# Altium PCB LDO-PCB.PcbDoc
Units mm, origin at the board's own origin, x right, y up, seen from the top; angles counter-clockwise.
Board outline 26 x 11 mm, 2 copper layers (Top Layer, Bottom Layer); 5 components, 3 nets, 17 pads, 4 vias.
Unrouted connection lines stored in the file: 4.
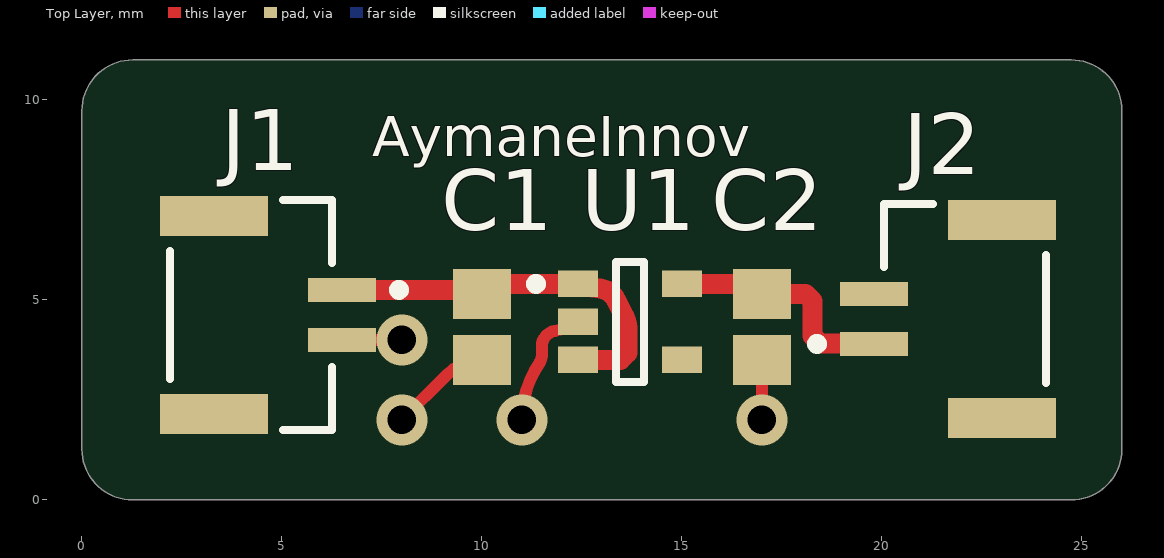
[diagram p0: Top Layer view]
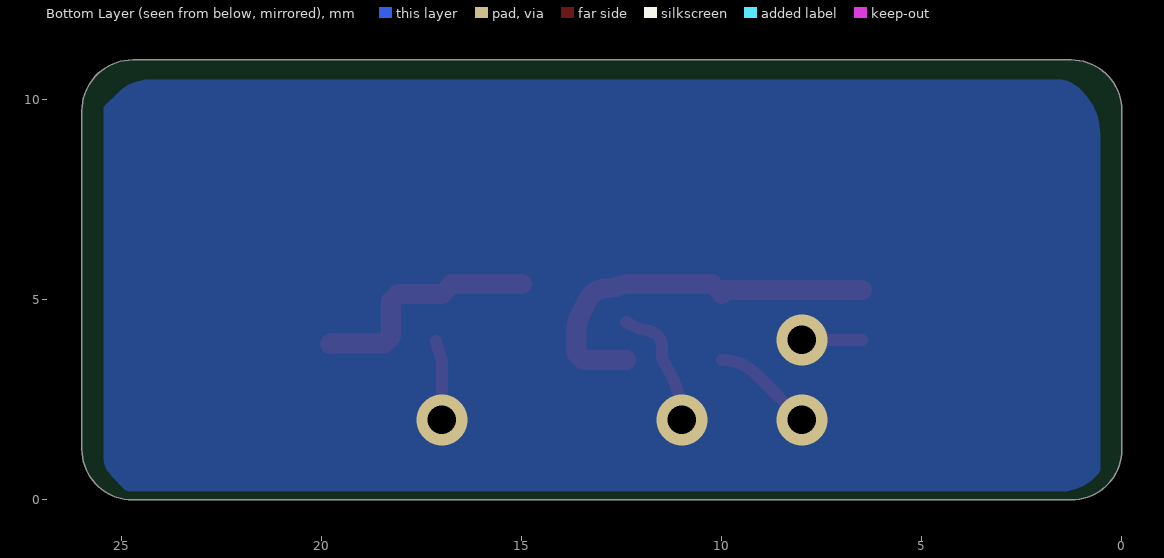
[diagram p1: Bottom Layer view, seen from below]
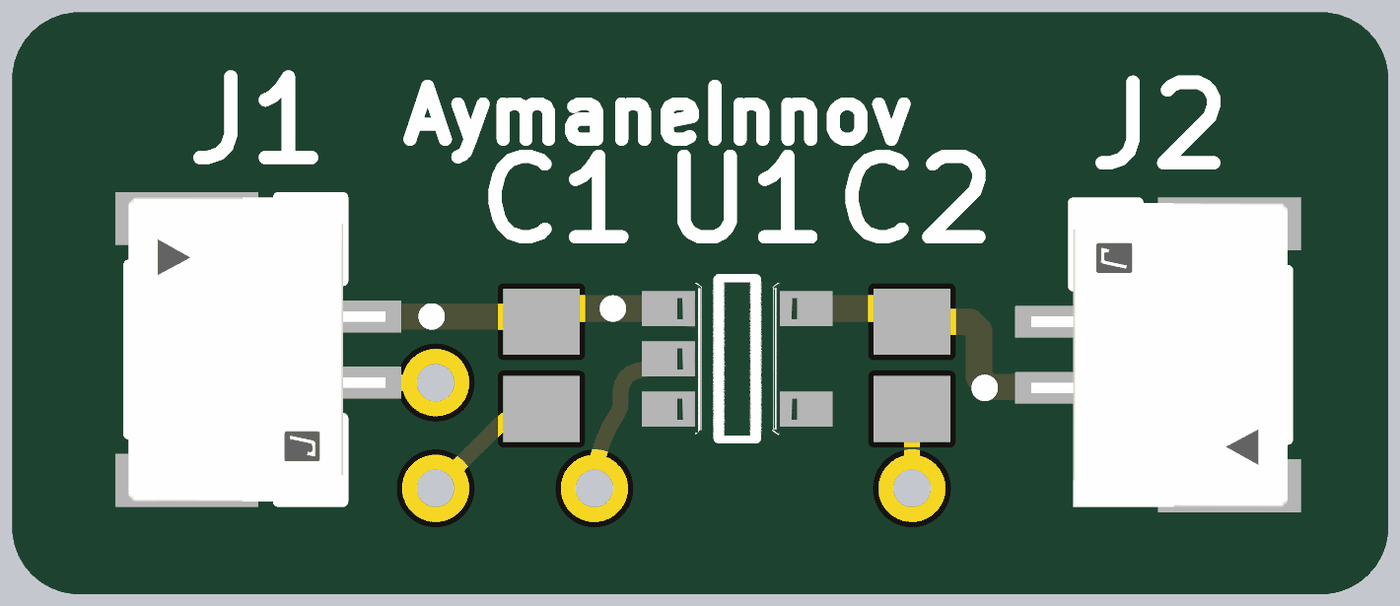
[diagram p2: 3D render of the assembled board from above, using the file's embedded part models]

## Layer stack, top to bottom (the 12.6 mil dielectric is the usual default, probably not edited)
Top Solder: solder mask 0.0102, Solder Resist, Dk 3.5
Top Layer: signal copper 0.0356
Dielectric 1: dielectric 0.32, FR-4, Dk 4.8
Bottom Layer: signal copper 0.0356
Bottom Solder: solder mask 0.0102, Solder Resist, Dk 3.5

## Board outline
0,1.27 ccw(c1.27,1.27) 1.27,0 24.73,0 ccw(c24.73,1.27) 26,1.27 26,9.73 ccw(c24.73,9.73) 24.73,11 1.27,11 ccw(c1.27,9.73) 0,9.73

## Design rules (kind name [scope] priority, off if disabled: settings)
Clearance [All] p1: gap=0.254 ignorepadtopadclearanceinfootprint=FALSE
PolygonConnect [All] p1: connectstyle=Relief reliefconductorwidth=0.254 reliefentries=4 polygonreliefangle="90 Angle" airgapwidth=0.254
RoutingVias [All] p1: holewidth=0.711 width=1.27 viastyle="Through Hole" minholewidth=0.711 minwidth=1.27 maxholewidth=0.711 maxwidth=1.27
SolderMaskExpansion [All] p1: expansion=0.102 istentingtop=FALSE
SupplyNets "Schematic Supply Nets_2" [InNet('GND')] p1: voltage=0.000
SupplyNets "Schematic Supply Nets_1" [InNet('+3V3')] p2: voltage=0.000
SupplyNets "Schematic Supply Nets" [InNet('+5V')] p3: voltage=0.000
Width [All] p1: maxlimit=0.5 minlimit=0.254 preferedwidth=0.3
30 further rules are at their usual default settings.

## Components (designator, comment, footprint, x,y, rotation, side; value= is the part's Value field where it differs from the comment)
C1 "1 µF" CAPC2013X145X50NL20T20 10,4.325 r90 top
C2 "1 µF" CAPC2013X145X50NL20T20 17,4.325 r90 top
J1 "SM02B-GHS-TB(LF)(SN)" FP-SM02B-GHS-TB_LF_SN-MFG 4.225,4.625 r270 top
J2 "SM02B-GHS-TB(LF)(SN)" FP-SM02B-GHS-TB_LF_SN-MFG 22.075,4.525 r90 top
U1 "MIC5317-3.3YM5-TR" FP-SOT23-5LD-PL-1-MFG 13.7,4.45 r0 top

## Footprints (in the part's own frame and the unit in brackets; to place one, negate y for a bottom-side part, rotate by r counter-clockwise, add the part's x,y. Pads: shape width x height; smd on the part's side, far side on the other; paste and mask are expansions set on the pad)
CAPC2013X145X50NL20T20 [mm] "Chip Capacitor, 2-Leads, Body 2.00x1.25mm, IPC Medium Density"
  rect 1.25x1.45 smd: 1(-0.825,0) 2(0.825,0)
  body extent -1.1,-0.72 1.1,0.72, height 1.45
FP-SM02B-GHS-TB_LF_SN-MFG [mm]
  rect 0.6x1.7 smd paste+0 mask+0: 1(-0.625,2.275) 2(0.625,2.275)
  rect 1x2.7 smd paste+0 mask+0: 3(-2.475,-0.925) 4(2.475,-0.925)
  silkscreen extent -2.88,-2.02 2.88,3.83, body extent -3.08,-2.37 3.08,3.22, height 0.25
FP-SOT23-5LD-PL-1-MFG [mm]
  rect 1x0.66 smd paste+0 mask+0: 1(-1.3,0.95) 2(-1.3,0) 3(-1.3,-0.95) 4(1.3,-0.95) 5(1.3,0.95)
  silkscreen extent -2.47,-1.5 0.35,1.5, body extent -1.9,-1.6 1.9,1.6, height 0.25

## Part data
C1 C2: library part CMP-2007-01676-1, Manufacturer=Vitramon, Part Number=VJ0805Y105KXQRW1BC
J1 J2: library part CMP-2000-07076-2, "CONN HEADER SMD R/A 2POS 1.25MM", Color=Natural, Current Rating=1A, Package Quantity=2500, Voltage Rating=50V
U1: library part CMP-06324-000116-1, "IC REG LINEAR 3.3V 150MA SOT23-5", Case/Package=SOT-23-5, Dropout Voltage=155mV, Max Input Voltage=6V, Max Operating Temperature=125°C, Min Current Limit=200mA, Min Input Voltage=2.5V, Min Operating Temperature=-40°C, Output Current=150mA, Output Voltage=3.3V, Package Quantity=3000, Power Supply Rejection Ratio (PSRR)=70dB

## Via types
v1: diameter 1.27, hole 0.711, Top Layer to Bottom Layer, 4 vias

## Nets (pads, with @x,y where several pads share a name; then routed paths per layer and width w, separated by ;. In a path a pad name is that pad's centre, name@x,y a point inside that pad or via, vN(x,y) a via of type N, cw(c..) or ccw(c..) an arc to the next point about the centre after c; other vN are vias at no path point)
+3V3: C2.2 J2.1 U1.5 | length 5.9
  Top Layer w0.5: U1.5 16.75,5.4 C2.2 18.092,5.15 18.268,4.974 18.268,4.092 18.444,3.916 19.784,3.916 J2.1
+5V: C1.2 J1.1 U1.1 U1.3 | length 9.6
  Top Layer w0.5: J1.1 9.9,5.25 C1.2 10.25,5.4 U1.1 12.65,5.32 12.964,5.28 cw(c12.9,4.78) 13.351,5.004 13.552,4.599 ccw(c14.5,5.07) 13.573,4.559 cw(c13.135,4.318) 13.635,4.318 13.635,3.676 ; U1.3 13.46,3.5
GND: C1.1 C2.1 J1.2 J2.2 U1.2 | length 9.2
  Top Layer w0.3: J1.2 v1(8,4) ; v1(8,2) 9.146,3.146 cw(c10,2.293) C1.1 ; v1(11,2) cw(c13.535,2) 11.444,3.433 ccw(c11.196,3.602) 11.496,3.602 11.496,3.83 cw(c11.9,3.83) 11.824,4.227 12.05,4.27 U1.2 ; v1(17,2) C2.1 C2.1@17.154,3.975
pads on no net: J1.3 J1.4 J2.3 J2.4 U1.4
copper on no net: | length 0.2
  Top Layer w0.5: 13.46,3.5 13.635,3.676

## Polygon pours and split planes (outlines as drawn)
no net on Bottom Layer "NONET_L02_P001" (solid, pour order 1): 0.545,9.13 cw(c2.08,9.13) 0.995,10.216 1.078,10.299 cw(c1.568,9.808) 1.568,10.502 24.326,10.502 cw(c24.326,9.415) 25.095,10.184 25.427,9.852 cw(c25.363,9.788) 25.453,9.788 25.453,1.097 cw(c24.697,1.097) 25.232,0.563 24.936,0.268 cw(c24.825,0.38) 24.825,0.222 1.495,0.222 cw(c1.495,1.355) 0.693,0.553 0.589,0.657 cw(c0.696,0.764) 0.545,0.764 0.545,9.132

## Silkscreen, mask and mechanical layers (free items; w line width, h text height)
Top Overlay:
  text "AymaneInnov" at 7.254,8.587 h1
Bottom Solder:
  lines w0.254: 0,1.27 ccw(c1.27,1.27) 1.27,0 13,0 24.73,0 ccw(c24.73,1.27) 26,1.27 26,9.73 ccw(c24.73,9.73) 24.73,11 1.27,11 ccw(c1.27,9.73) 0,9.73 0,1.27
